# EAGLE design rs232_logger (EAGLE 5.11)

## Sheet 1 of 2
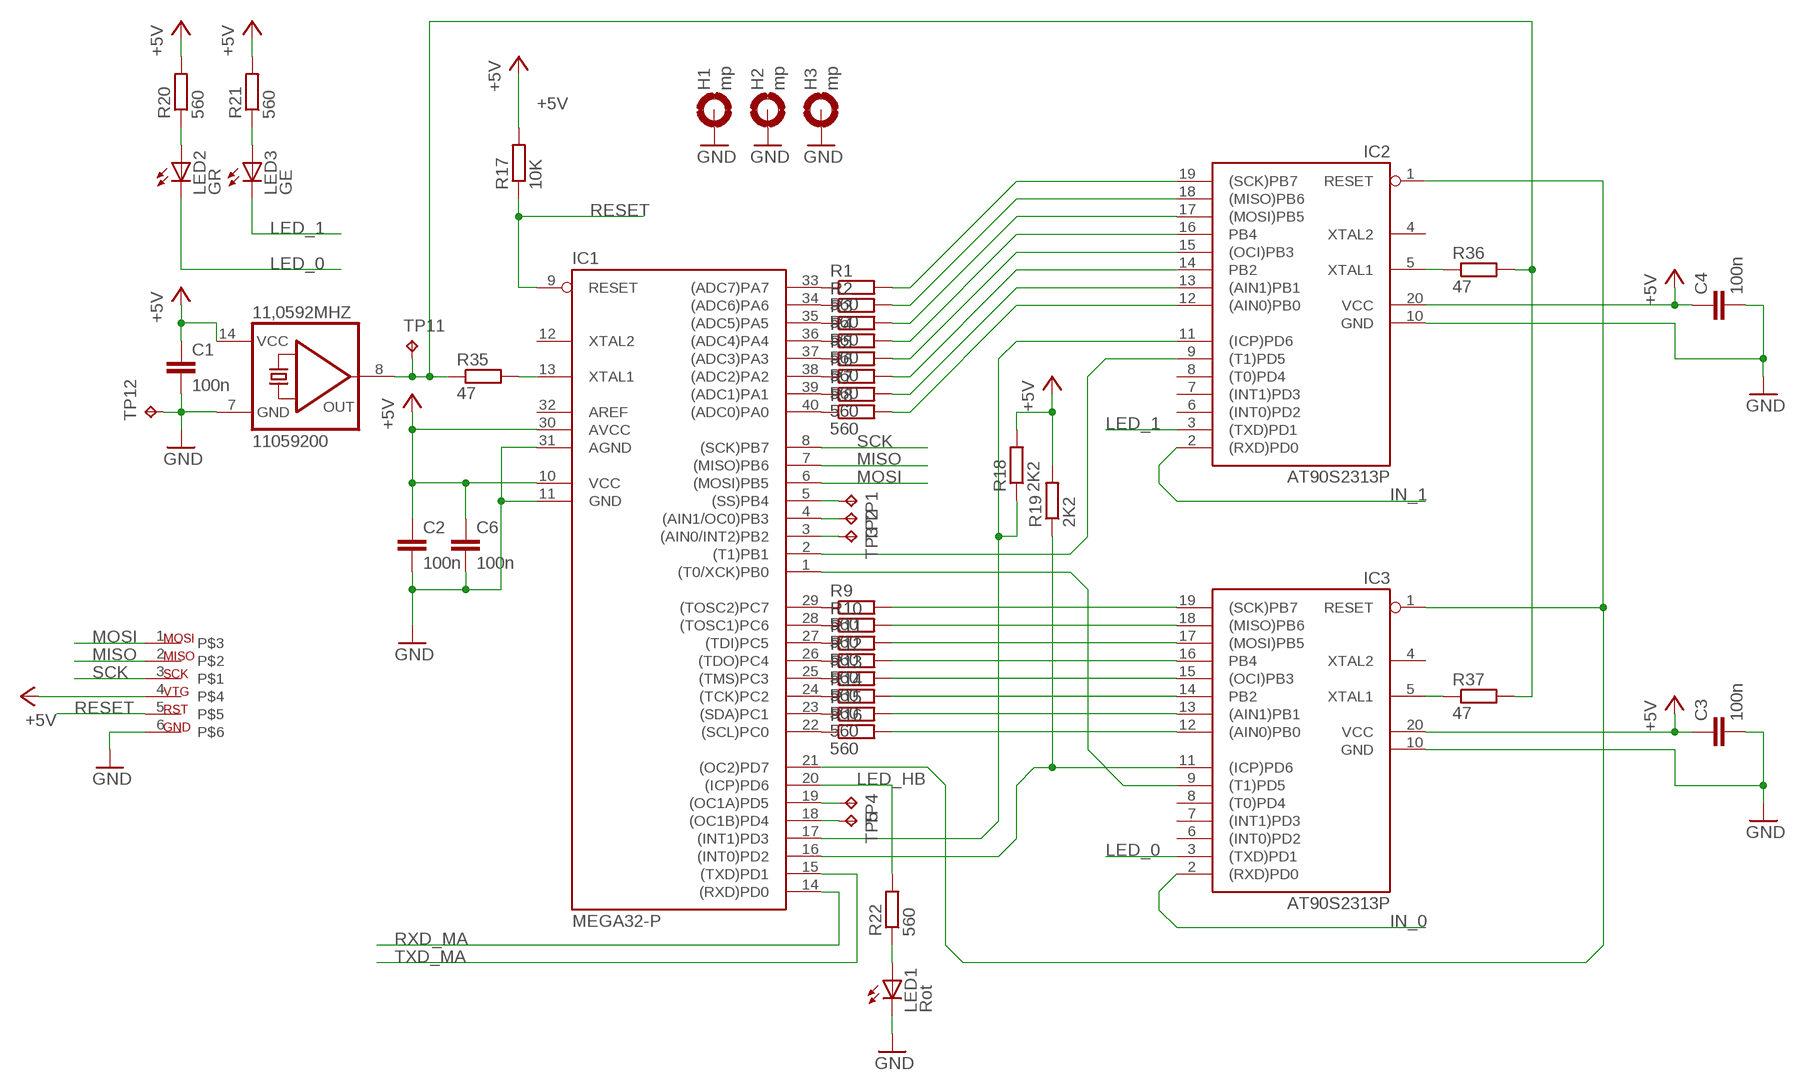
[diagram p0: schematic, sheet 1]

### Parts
11,0592MHZ  11059200  QG5860  [DIL14S]
C1  100n  C-EU050-024X044  [C050-024X044]
C2  100n  C-EU025-024X044  [C025-024X044]
C3  100n  C-EU050-024X044  [C050-024X044]
C4  100n  C-EU050-024X044  [C050-024X044]
C6  100n  C-EU025-024X044  [C025-024X044]
H1  mp  MOUNT-PAD-ROUND3.2  [3,2-PAD]
H2  mp  MOUNT-PAD-ROUND3.2  [3,2-PAD]
H3  mp  MOUNT-PAD-ROUND3.2  [3,2-PAD]
IC1  MEGA32-P  [DIL40]
IC2  AT90S2313P  [DIL20]
IC3  AT90S2313P  [DIL20]
LED1  Rot  LED5MM  [LED5MM]
LED2  GR  LED5MM  [LED5MM]
LED3  GE  LED5MM  [LED5MM]
R1  560  0207/10/LF  [0207/10/LF]
R2  560  0207/10/LF  [0207/10/LF]
R3  560  0207/10/LF  [0207/10/LF]
R4  560  0207/10/LF  [0207/10/LF]
R5  560  0207/10/LF  [0207/10/LF]
R6  560  0207/10/LF  [0207/10/LF]
R7  560  0207/10/LF  [0207/10/LF]
R8  560  0207/10/LF  [0207/10/LF]
R9  560  0207/10/LF  [0207/10/LF]
R10  560  0207/10/LF  [0207/10/LF]
R11  560  0207/10/LF  [0207/10/LF]
R12  560  0207/10/LF  [0207/10/LF]
R13  560  0207/10/LF  [0207/10/LF]
R14  560  0207/10/LF  [0207/10/LF]
R15  560  0207/10/LF  [0207/10/LF]
R16  560  0207/10/LF  [0207/10/LF]
R17  10K  R-EU_0207/10  [0207/10]
R18  2K2  R-EU_0207/10  [0207/10]
R19  2K2  R-EU_0207/10  [0207/10]
R20  560  R-EU_0207/10  [0207/10]
R21  560  R-EU_0207/10  [0207/10]
R22  560  R-EU_0207/10  [0207/10]
R35  47  R-EU_0207/10  [0207/10]
R36  47  R-EU_0207/10  [0207/10]
R37  47  R-EU_0207/10  [0207/10]
TP1  TPPAD1-13Y  [P1-13Y]
TP2  TPPAD1-13Y  [P1-13Y]
TP3  TPPAD1-13Y  [P1-13Y]
TP4  TPPAD1-13Y  [P1-13Y]
TP5  TPPAD1-13Y  [P1-13Y]
TP11  TPPAD1-13  [P1-13]
TP12  TPPAD1-13  [P1-13]
U$1  ISP_6  [M_ISP_6]

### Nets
+5V: 11,0592MHZ.14(VCC) C1.1 C2.1 C3.1 C4.1 C6.1 IC1.10(VCC) IC1.30(AVCC) IC2.20(VCC) IC3.20(VCC) R17.2 R18.2 R19.2 R20.2 R21.2 U$1.4 ; also sheet 2
GND: 11,0592MHZ.7(GND) C1.2 C2.2 C3.2 C4.2 C6.2 H1.B3,2(MOUNT) H2.B3,2(MOUNT) H3.B3,2(MOUNT) IC1.11(GND) IC1.31(AGND) IC2.10(GND) IC3.10(GND) LED1.K(C) TP12.TP U$1.6 ; also sheet 2
IN_0: IC3.2((RXD)PD0) ; also sheet 2
IN_1: IC2.2((RXD)PD0) ; also sheet 2
LED_0: IC3.3((TXD)PD1) LED2.K(C)
LED_1: IC2.3((TXD)PD1) LED3.K(C)
LED_HB: IC1.20((ICP)PD6) R22.2
MISO: IC1.7((MISO)PB6) U$1.2
MOSI: IC1.6((MOSI)PB5) U$1.1
N$1: IC1.33((ADC7)PA7) R1.1
N$2: IC1.34((ADC6)PA6) R2.1
N$3: IC1.35((ADC5)PA5) R3.1
N$4: IC1.36((ADC4)PA4) R4.1
N$5: IC1.37((ADC3)PA3) R5.1
N$6: IC1.38((ADC2)PA2) R6.1
N$7: IC1.39((ADC1)PA1) R7.1
N$8: IC1.40((ADC0)PA0) R8.1
N$9: IC1.29((TOSC2)PC7) R9.1
N$10: IC1.28((TOSC1)PC6) R10.1
N$11: IC1.27((TDI)PC5) R11.1
N$12: IC1.26((TDO)PC4) R12.1
N$13: IC1.25((TMS)PC3) R13.1
N$14: IC1.24((TCK)PC2) R14.1
N$15: IC1.23((SDA)PC1) R15.1
N$16: IC1.22((SCL)PC0) R16.1
N$17: IC2.19((SCK)PB7) R1.2
N$18: IC2.18((MISO)PB6) R2.2
N$19: IC2.17((MOSI)PB5) R3.2
N$20: IC2.16(PB4) R4.2
N$21: IC2.15((OCI)PB3) R5.2
N$22: IC2.14(PB2) R6.2
N$23: IC2.13((AIN1)PB1) R7.2
N$24: IC2.12((AIN0)PB0) R8.2
N$25: IC3.19((SCK)PB7) R9.2
N$26: IC3.18((MISO)PB6) R10.2
N$27: IC3.17((MOSI)PB5) R11.2
N$28: IC3.16(PB4) R12.2
N$29: IC3.15((OCI)PB3) R13.2
N$30: IC3.14(PB2) R14.2
N$31: IC3.13((AIN1)PB1) R15.2
N$32: IC3.12((AIN0)PB0) R16.2
N$33: 11,0592MHZ.8(OUT) R35.1 R36.2 R37.2 TP11.TP
N$34: IC1.21((OC2)PD7) IC2.1(RESET) IC3.1(RESET)
N$35: IC1.16((INT0)PD2) IC3.11((ICP)PD6) R19.1
N$36: IC1.17((INT1)PD3) IC2.11((ICP)PD6) R18.1
N$37: IC1.1((T0/XCK)PB0) IC3.9((T1)PD5)
N$38: IC1.2((T1)PB1) IC2.9((T1)PD5)
N$39: IC1.13(XTAL1) R35.2
N$42: IC2.5(XTAL1) R36.1
N$44: LED2.A R20.1
N$45: IC3.5(XTAL1) R37.1
N$46: LED3.A R21.1
N$48: IC1.18((OC1B)PD4) TP5.TP
N$49: LED1.A R22.1
N$50: IC1.19((OC1A)PD5) TP4.TP
N$52: IC1.3((AIN0/INT2)PB2) TP3.TP
N$53: IC1.4((AIN1/OC0)PB3) TP2.TP
N$54: IC1.5((SS)PB4) TP1.TP
RESET: IC1.9(RESET) R17.1 U$1.5
RXD_MA: IC1.14((RXD)PD0) ; also sheet 2
SCK: IC1.8((SCK)PB7) U$1.3
TXD_MA: IC1.15((TXD)PD1) ; also sheet 2
Unconnected: IC1.12(XTAL2) IC2.4(XTAL2) IC2.6((INT0)PD2) IC2.7((INT1)PD3) IC2.8((T0)PD4) IC3.4(XTAL2) IC3.6((INT0)PD2) IC3.7((INT1)PD3) IC3.8((T0)PD4)

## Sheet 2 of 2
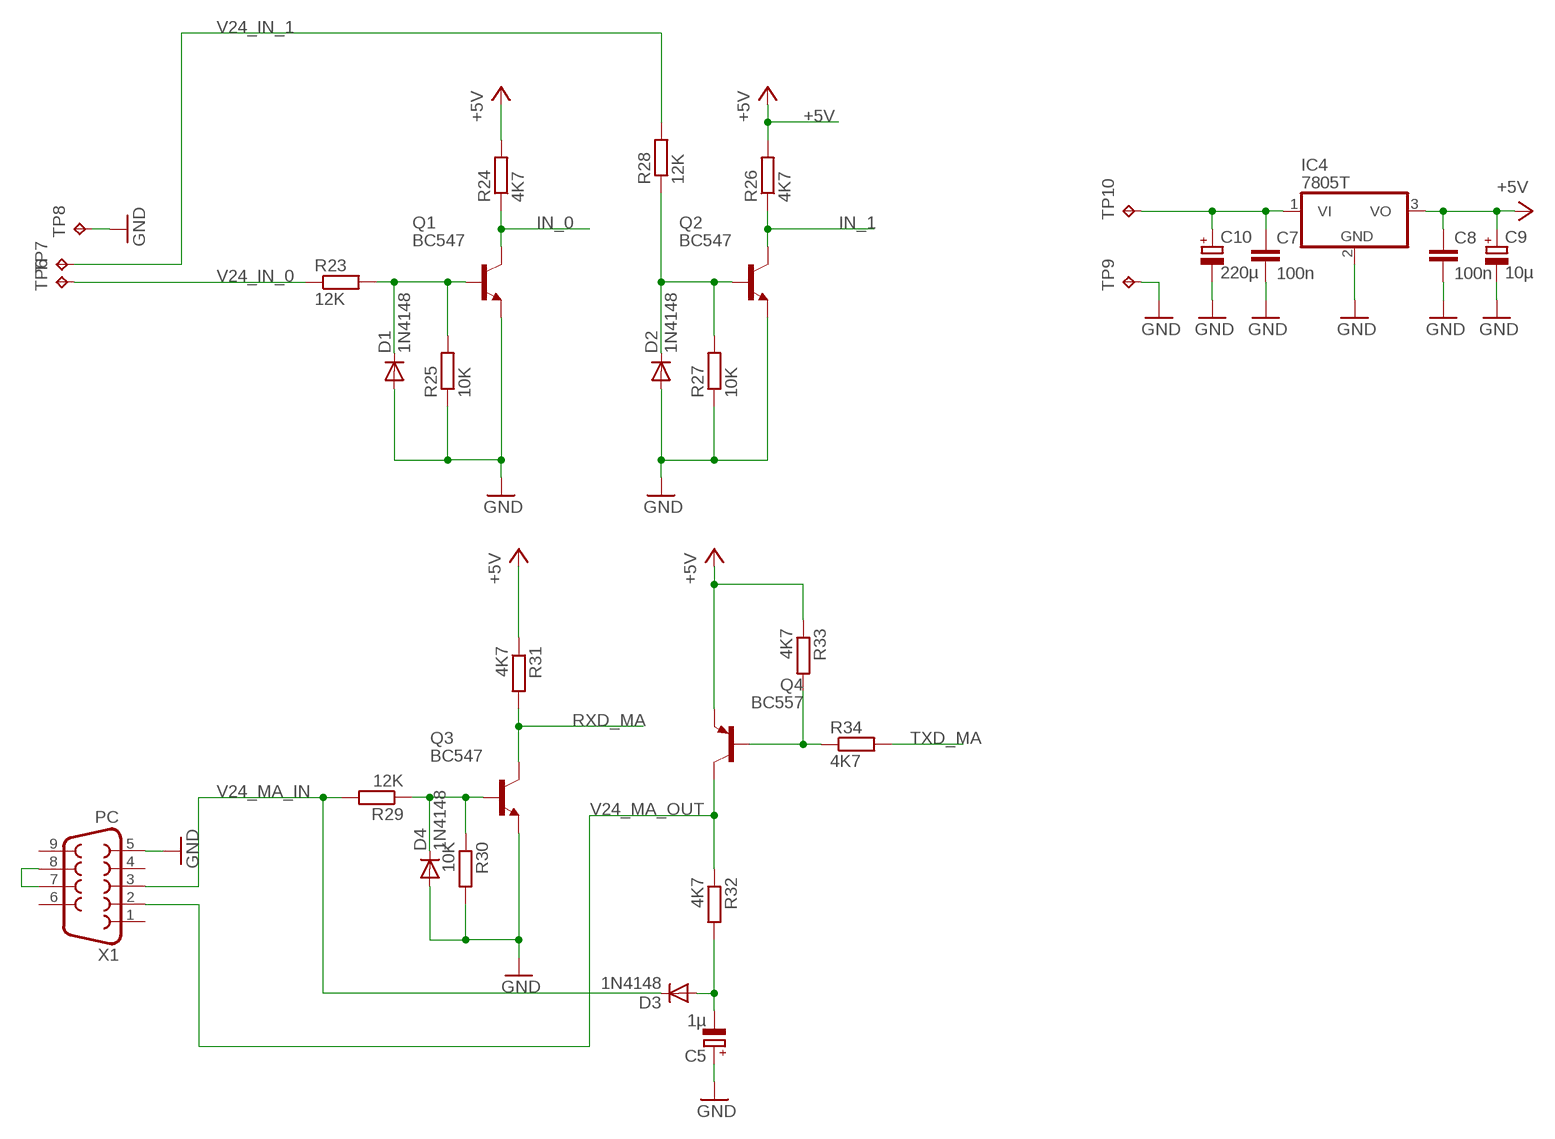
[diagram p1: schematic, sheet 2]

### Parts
C5  1µ  CPOL-EUE2.5-5  [E2,5-5]
C7  100n  C-EU050-024X044  [C050-024X044]
C8  100n  C-EU050-024X044  [C050-024X044]
C9  10µ  CPOL-EUE3.5-8  [E3,5-8]
C10  220µ  CPOL-EUE5-13  [E5-13]
D1  1N4148  1N4148DO35-10  [DO35-10]
D2  1N4148  1N4148DO35-10  [DO35-10]
D3  1N4148  1N4148DO35-10  [DO35-10]
D4  1N4148  1N4148DO35-10  [DO35-10]
IC4  7805T  [TO220H]
Q1  BC547  [TO92-CBE]
Q2  BC547  [TO92-CBE]
Q3  BC547  [TO92-CBE]
Q4  BC557  [TO92-CBE]
R23  12K  R-EU_0207/10  [0207/10]
R24  4K7  R-EU_0207/10  [0207/10]
R25  10K  R-EU_0207/10  [0207/10]
R26  4K7  R-EU_0207/10  [0207/10]
R27  10K  R-EU_0207/10  [0207/10]
R28  12K  R-EU_0207/10  [0207/10]
R29  12K  R-EU_0207/10  [0207/10]
R30  10K  R-EU_0207/10  [0207/10]
R31  4K7  R-EU_0207/10  [0207/10]
R32  4K7  R-EU_0207/10  [0207/10]
R33  4K7  R-EU_0207/10  [0207/10]
R34  4K7  R-EU_0207/10  [0207/10]
TP6  TPPAD1-13Y  [P1-13Y]
TP7  TPPAD1-13Y  [P1-13Y]
TP8  TPPAD1-13Y  [P1-13Y]
TP9  TPPAD1-13Y  [P1-13Y]
TP10  TPPAD1-13Y  [P1-13Y]
X1  PC  F09HP  [F09HP]

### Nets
+5V: C8.1 C9.+ IC4.3(VO) Q4.E R24.2 R26.2 R31.1 R33.1 ; also sheet 1
GND: C5.+ C7.2 C8.2 C9.- C10.- D1.A D2.A D4.A IC4.2(GND) Q1.E Q2.E Q3.E R25.1 R27.1 R30.2 TP8.TP TP9.TP X1.5 ; also sheet 1
IN_0: Q1.C R24.1 ; also sheet 1
IN_1: Q2.C R26.1 ; also sheet 1
N$40: D1.C Q1.B R23.2 R25.2
N$41: C5.- D3.A R32.2
N$43: D2.C Q2.B R27.2 R28.1
N$47: X1.7 X1.8
N$51: D4.C Q3.B R29.1 R30.1
N$56: C7.1 C10.+ IC4.1(VI) TP10.TP
N$57: Q4.B R33.2 R34.1
RXD_MA: Q3.C R31.2 ; also sheet 1
TXD_MA: R34.2 ; also sheet 1
V24_IN_0: R23.1 TP6.TP
V24_IN_1: R28.2 TP7.TP
V24_MA_IN: D3.C R29.2 X1.3
V24_MA_OUT: Q4.C R32.1 X1.2
Unconnected: X1.1 X1.4 X1.6 X1.9

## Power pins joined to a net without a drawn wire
AREF: IC1.32(AREF)

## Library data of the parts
11,0592MHZ = crystal:QG5860: CRYSTAL RESONATOR; OC_FARNELL: unknown; OC_NEWARK: unknown
C1-C4 C6-C8 = !_my_res:C-EU: CAPACITOR, European symbol
C5 = resistor:CPOL-EU: POLARIZED CAPACITOR, European symbol
C9 C10 = !_my_res:CPOL-EU: POLARIZED CAPACITOR, European symbol
D1-D4 = diode:1N4148: DIODE
H1-H3 = holes:MOUNT-PAD-ROUND: MOUNTING PAD, round
IC1 = avr-7:MEGA32-P: MICROCONTROLLER 32 Kbytes FLASH 2 Kbytes SRAM 1 Kbytes EEPROM USART 8-channel 10 bit ADC
IC2 IC3 = atmel:AT90S2313: MICROCONTROLLER 2 Kbytes FLASH 128 bytes SRAM 128 bytes EEPROM UART
IC4 = linear_1:78*: Positive VOLTAGE REGULATOR Source: http://cache.national.com/ds/LM/LM78L05.pdf http://www.fairchildsemi.com/ds/LM/LM7805.pdf
LED1-LED3 = led:LED: LED
Q1-Q3 = !_my_semi:BC547
Q4 = !_my_semi:BC557
R1-R16 = !_my_res:0207/10/LF
R17-R37 = !_my_res:R-EU_: RESISTOR, European symbol
TP1-TP12 = testpad:TP: Test pad
U$1 = !_mylib:ISP_6
X1 = con-subd:F09: SUB-D

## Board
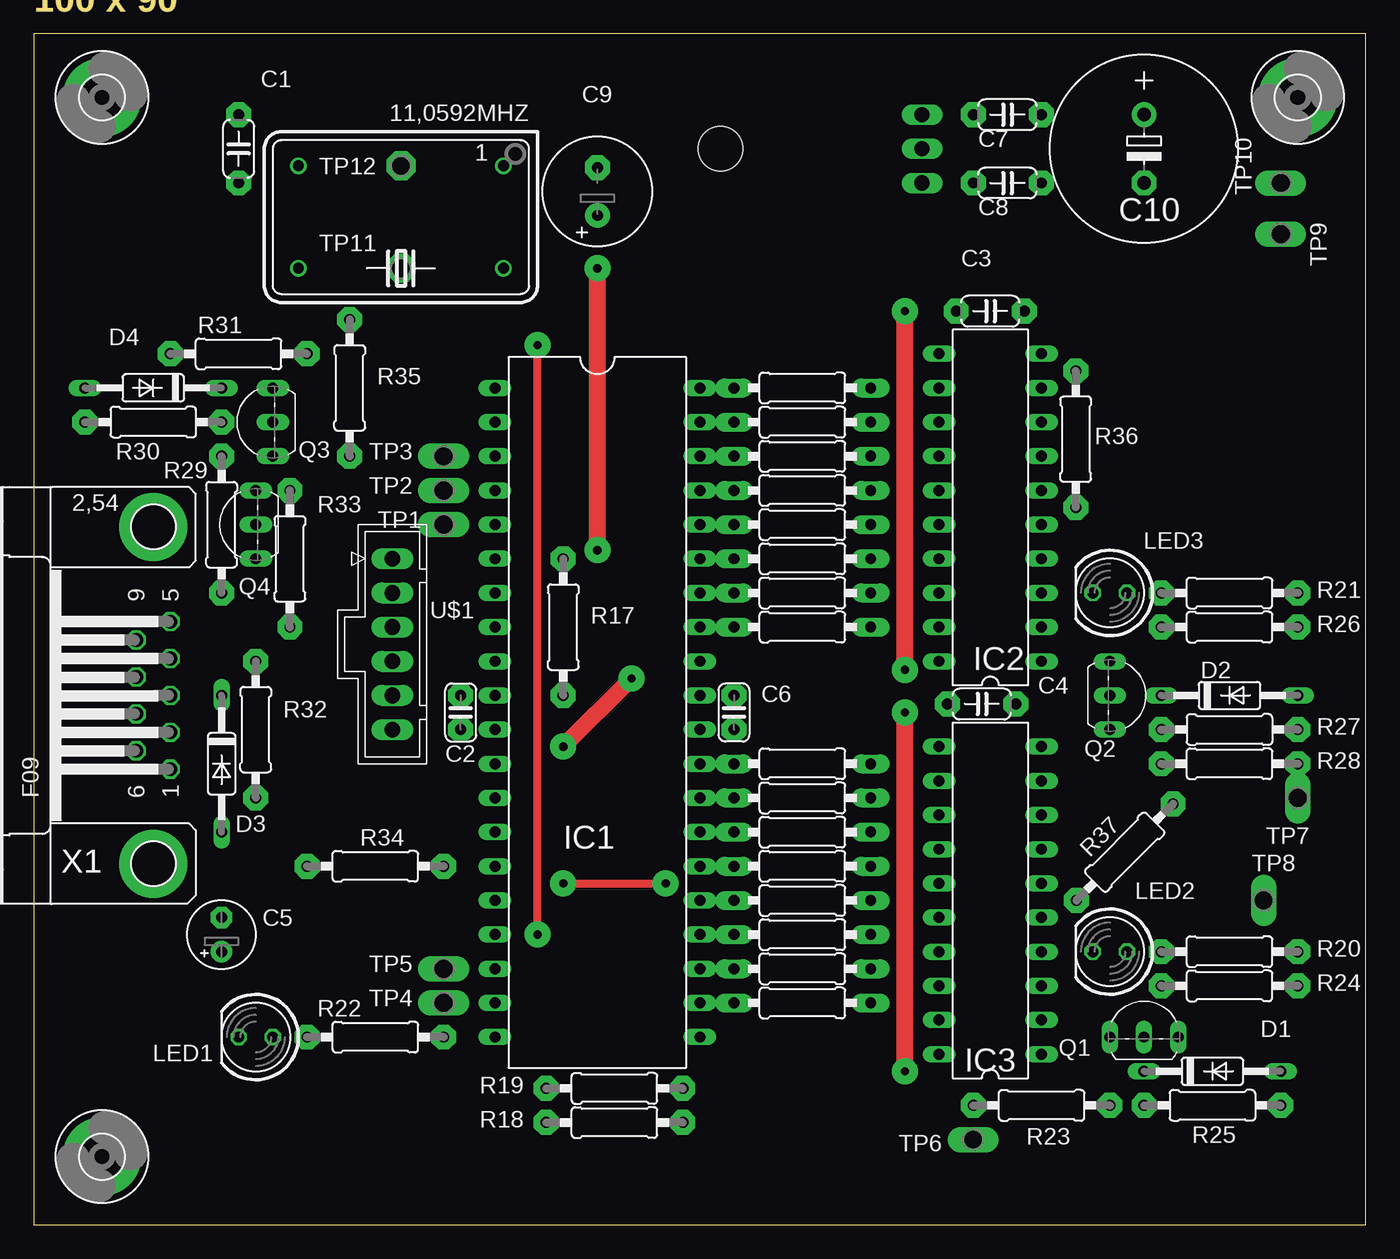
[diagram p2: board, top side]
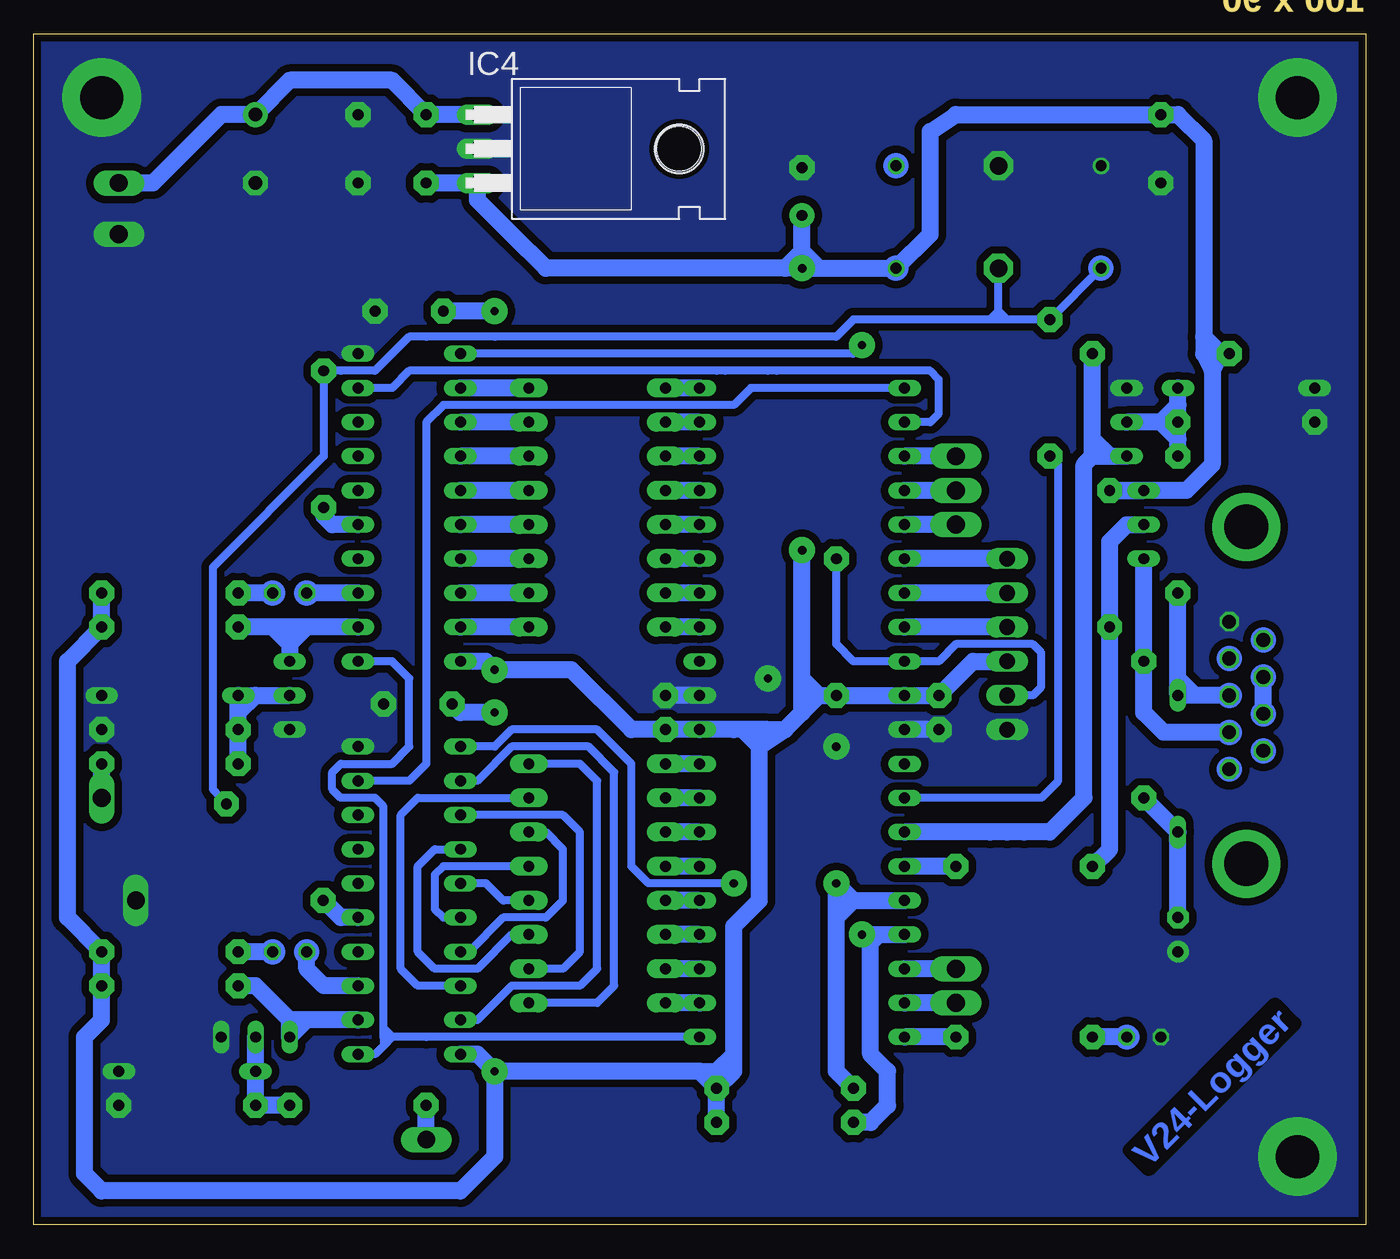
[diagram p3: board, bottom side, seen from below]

Size 99.04 x 88.57 mm. Coordinates in mm from the lower left corner, seen from the top.
Outline: 0,0 99.04,0 99.04,88.57 0,88.57 0,0
Copper layers (1*16): Top 0.035mm / dielectric 1.5mm / Bottom 0.035mm
Design rules "ths 01 and 02 layers": minimum track width 6mil, minimum drill 0.3mm, track to track 6mil, track to pad 6mil, pad to pad 6mil, via to via 6mil, smd to smd 6mil, copper to edge 2mil, drill to drill 10mil, minimum pad ring 8mil, minimum via ring 6mil, stop-mask expansion 3mil, vias tented up to drill 0mil, thermal gap 8mil

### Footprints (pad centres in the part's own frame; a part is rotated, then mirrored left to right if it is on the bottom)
DIL14S = drill 0.813 round: 1 -7.62,-3.81; 7 7.62,-3.81; 8 7.62,3.81; 14 -7.62,3.81
C050-024X044 = drill 0.813 pad 1.85 octagon: 1 -2.54,0; 2 2.54,0
C025-024X044 = drill 0.813 pad 1.85 octagon: 1 -1.27,0; 2 1.27,0
E2,5-5 = drill 0.813 pad 1.6 round: + -1.27,0 | drill 0.813 pad 1.6 octagon: - 1.27,0
E3,5-8 = drill 0.813 pad 1.85 round: + -1.778,0 | drill 0.813 pad 1.85 octagon: - 1.778,0
E5-13 = drill 1.016 pad 1.85 round: + -2.54,0 | drill 1.016 pad 1.85 octagon: - 2.54,0
DO35-10 = drill 0.813 long: A 5.08,0; C -5.08,0
3,2-PAD = drill 3.2 pad 5.842 round: B3,2 0,0
DIL40 = drill 0.813 long: 1 -24.13,-7.62; 2 -21.59,-7.62; 3 -19.05,-7.62; 4 -16.51,-7.62; 5 -13.97,-7.62; 6 -11.43,-7.62; 7 -8.89,-7.62; 8 -6.35,-7.62; 9 -3.81,-7.62; 10 -1.27,-7.62; 11 1.27,-7.62; 12 3.81,-7.62; 13 6.35,-7.62; 14 8.89,-7.62; 15 11.43,-7.62; 16 13.97,-7.62; 17 16.51,-7.62; 18 19.05,-7.62; 19 21.59,-7.62; 20 24.13,-7.62; 21 24.13,7.62; 22 21.59,7.62; 23 19.05,7.62; 24 16.51,7.62; 25 13.97,7.62; 26 11.43,7.62; 27 8.89,7.62; 28 6.35,7.62; 29 3.81,7.62; 30 1.27,7.62; 31 -1.27,7.62; 32 -3.81,7.62; 33 -6.35,7.62; 34 -8.89,7.62; 35 -11.43,7.62; 36 -13.97,7.62; 37 -16.51,7.62; 38 -19.05,7.62; 39 -21.59,7.62; 40 -24.13,7.62
DIL20 = drill 0.813 long: 1 -11.43,-3.81; 2 -8.89,-3.81; 3 -6.35,-3.81; 4 -3.81,-3.81; 5 -1.27,-3.81; 6 1.27,-3.81; 7 3.81,-3.81; 8 6.35,-3.81; 9 8.89,-3.81; 10 11.43,-3.81; 11 11.43,3.81; 12 8.89,3.81; 13 6.35,3.81; 14 3.81,3.81; 15 1.27,3.81; 16 -1.27,3.81; 17 -3.81,3.81; 18 -6.35,3.81; 19 -8.89,3.81; 20 -11.43,3.81
TO220H = drill 1.118 long: 1 -2.54,-10.16; 2 0,-10.16; 3 2.54,-10.16 | hole 3.302: 0,4.826
LED5MM = drill 0.813 octagon: A -1.27,0; K 1.27,0
TO92-CBE = drill 0.813 long: B 0,0; C -2.54,0; E 2.54,0
0207/10/LF = drill 0.813 pad 1.397 long: 1 -5.08,0; 2 5.08,0
0207/10 = drill 0.813 pad 1.85 octagon: 1 -5.08,0; 2 5.08,0
P1-13Y = drill 1.321 pad 1.905 long: TP 0,0
P1-13 = drill 1.321 pad 2.159 octagon: TP 0,0
M_ISP_6 = drill 1.168 long: 1 0,0; 2 2.54,0; 3 5.08,0; 4 7.62,0; 5 10.16,0; 6 12.7,0
F09HP = drill 1.016 octagon: 1 -5.486,-1.27; 2 -2.743,-1.27; 3 0,-1.27; 4 2.743,-1.27; 5 5.486,-1.27; 6 -4.115,1.27; 7 -1.372,1.27; 8 1.372,1.27; 9 4.115,1.27 | drill 3.302 pad 5.08 round: G1 -12.522,0; G2 12.522,0

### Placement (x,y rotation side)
11,0592MHZ  27.3,74.93 180 top
C1  15.24,80.01 270 top
C2  31.75,38.1 270 top
C3  71.12,67.94 0 top
C4  70.48,38.73 0 top
C5  13.97,21.59 90 top
C6  52.07,38.1 90 top
C7  72.39,82.55 0 top
C8  72.39,77.47 0 top
C9  41.91,76.83 90 top
C10  82.55,80.01 270 top
D1  87.63,11.43 0 top
D2  88.9,39.37 0 top
D3  13.97,34.29 270 top
D4  8.89,62.23 180 top
H1  5.08,83.82 0 top
H2  5.08,5.08 0 top
H3  93.98,83.82 0 top
IC1  41.91,38.1 270 top
IC2  71.12,53.34 90 top
IC3  71.12,24.13 90 top
IC4  55.88,80.01 270 bottom
LED1  16.51,13.97 180 top
LED2  80.01,20.32 180 top
LED3  80.01,46.99 180 top
Q1  82.55,13.97 0 top
Q2  80.01,39.37 270 top
Q3  17.78,59.69 90 top
Q4  16.51,52.07 90 top
R1  57.15,44.45 0 top
R2  57.15,46.99 0 top
R3  57.15,49.53 0 top
R4  57.15,52.07 0 top
R5  57.15,54.61 0 top
R6  57.15,57.15 0 top
R7  57.15,59.69 0 top
R8  57.15,62.23 0 top
R9  57.15,34.29 0 top
R10  57.15,31.75 0 top
R11  57.15,29.21 0 top
R12  57.15,26.67 0 top
R13  57.15,24.13 0 top
R14  57.15,21.59 0 top
R15  57.15,19.05 0 top
R16  57.15,16.51 0 top
R17  39.37,44.45 270 top
R18  43.18,7.62 0 top
R19  43.18,10.16 0 top
R20  88.9,20.32 0 top
R21  88.9,46.99 0 top
R22  25.4,13.97 0 top
R23  74.93,8.89 0 top
R24  88.9,17.78 0 top
R25  87.63,8.89 180 top
R26  88.9,44.45 0 top
R27  88.9,36.83 180 top
R28  88.9,34.29 0 top
R29  13.97,52.07 270 top
R30  8.89,59.69 180 top
R31  15.24,64.77 0 top
R32  16.51,36.83 270 top
R33  19.05,49.53 270 top
R34  25.4,26.67 0 top
R35  23.5,62.23 270 top
R36  77.47,58.42 90 top
R37  81.12,27.72 45 top
TP1  30.48,52.07 90 top
TP2  30.48,54.61 90 top
TP3  30.48,57.15 90 top
TP4  30.48,16.51 90 top
TP5  30.48,19.05 90 top
TP6  69.85,6.35 90 top
TP7  93.98,31.75 180 top
TP8  91.44,24.13 0 top
TP9  92.71,73.66 270 top
TP10  92.71,77.47 90 top
TP11  27.3,71.12 0 top
TP12  27.3,78.74 0 top
U$1  26.67,49.53 270 top
X1  8.89,39.37 90 top

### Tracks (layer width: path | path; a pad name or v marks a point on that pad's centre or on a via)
+5V  (via drill 0.61 pad 1.93)
  Top 1.27: v64.77,11.43 v64.77,38.1 | v41.91,50.16 v41.91,71.12 | v64.77,41.27 v64.77,67.94
  Bottom 1.27: 43.18,36.83 41.91,38.1 | 41.91,38.1 40.64,39.37 | 40.64,39.37 R17.2 IC1.10 C2.1 29.21,41.91 U$1.4 | Q4.E R33.1 13.34,54.61 11.43,56.52 11.43,63.5 | R21.2 R26.2 96.52,41.91 96.52,22.86 R20.2 R24.2 93.98,15.24 95.25,13.97 95.25,3.81 93.98,2.54 67.31,2.54 64.77,5.08 v64.77,11.43 | R18.2 R19.2 | R19.2 49.53,11.43 | 49.53,11.43 v64.77,11.43 | 12.06,66.04 12.06,80.64 13.97,82.55 C1.1 30.48,82.55 32.38,81.28 32.38,73.66 11,0592MHZ.14 40.64,71.12 | 12.06,66.04 12.06,64.77 | 12.06,64.77 11.43,63.5 | v64.77,67.94 C3.1 | IC2.20 65.41,41.91 v64.77,41.27 59.05,41.27 54.61,36.83 C6.1 IC1.30 46.99,36.83 46.35,36.83 | C4.1 67.31,38.1 v64.77,38.1 | IC3.20 66.04,12.7 v64.77,11.43 | 44.45,36.83 46.35,36.83 | 44.45,36.83 43.18,36.83 | 45.09,35.56 45.09,24.13 46.99,22.23 46.99,12.7 | 45.09,35.56 44.45,36.83 | 46.99,12.7 46.99,11.43 R19.2 | 45.09,35.56 43.18,36.83 | 45.09,35.56 46.35,36.83 | 49.53,11.43 48.26,11.43 46.99,12.7 | 41.91,40.64 v41.91,50.16 | 40.64,39.37 41.91,40.64 | 41.91,38.1 41.91,40.64 | v41.91,71.12 43.18,71.12 | v41.91,71.12 43.18,71.12 | v41.91,71.12 40.64,71.12 | v41.91,71.12 60.96,71.12 63.5,73.66 66.04,76.2 IC4.3 C8.1 | v41.91,71.12 41.91,72.39 | 41.91,72.39 C9.+ | 40.64,71.12 41.91,72.39 | 43.18,71.12 41.91,72.39 | 12.06,64.77 10.79,64.77 | 10.79,64.77 R31.1 | 12.06,66.04 10.79,64.77 | 10.79,64.77 11.43,63.5
GND  (via drill 0.61 pad 1.93)
  Top 1.27: v39.37,35.56 v44.45,40.64
  Bottom 1.27: C2.2 IC1.11 | IC1.31 C6.2
  pour Bottom (isolate 0.559, rank 2, no thermals): -1.27,90.17 100.33,90.17 100.33,-1.27 -1.27,-1.27
IN_0
  Bottom 1.27: IC3.2 78.74,15.24 | 78.74,15.24 Q1.C 80.01,15.24 | 80.01,15.24 82.55,17.78 R24.1 | 78.74,15.24 80.01,15.24
IN_1
  Bottom 1.27: IC2.2 78.74,44.45 | 78.74,44.45 80.01,44.45 | 80.01,44.45 81.28,44.45 | 81.28,44.45 R26.1 | 80.01,44.45 80.01,43.18 | 80.01,43.18 Q2.C | 78.74,44.45 80.01,43.18 | 80.01,43.18 81.28,44.45
LED_0
  Bottom 1.27: IC3.3 77.47,17.78 78.74,19.05 LED2.K
LED_1
  Bottom 1.27: IC2.3 LED3.K
LED_HB
  Bottom 1.27: R22.2 IC1.20
MISO
  Bottom 1.27: U$1.2 IC1.7
MOSI
  Bottom 1.27: U$1.1 IC1.6
N$1
  Bottom 1.27: IC1.33 R1.1
N$2
  Bottom 1.27: IC1.34 R2.1
N$3
  Bottom 1.27: IC1.35 R3.1
N$4
  Bottom 1.27: IC1.36 R4.1
N$5
  Bottom 1.27: IC1.37 R5.1
N$6
  Bottom 1.27: IC1.38 R6.1
N$7
  Bottom 1.27: IC1.39 R7.1
N$8
  Bottom 1.27: IC1.40 R8.1
N$9
  Bottom 1.27: IC1.29 R9.1
N$10
  Bottom 1.27: IC1.28 R10.1
N$11
  Bottom 1.27: IC1.27 R11.1
N$12
  Bottom 1.27: IC1.26 R12.1
N$13
  Bottom 1.27: IC1.25 R13.1
N$14
  Bottom 1.27: IC1.24 R14.1
N$15
  Bottom 1.27: IC1.23 R15.1
N$16
  Bottom 1.27: IC1.22 R16.1
N$17
  Bottom 1.27: R1.2 IC2.19
N$18
  Bottom 1.27: R2.2 IC2.18
N$19
  Bottom 1.27: R3.2 IC2.17
N$20
  Bottom 1.27: R4.2 IC2.16
N$21
  Bottom 1.27: R5.2 IC2.15
N$22
  Bottom 1.27: R6.2 IC2.14
N$23
  Bottom 1.27: R7.2 IC2.13
N$24
  Bottom 1.27: R8.2 IC2.12
N$25
  Bottom 0.61: IC3.19 66.04,15.24 63.5,17.78 58.42,17.78 57.15,19.05 57.15,33.02 58.42,34.29 R9.2
N$26
  Bottom 0.61: R10.2 70.48,31.75 71.75,30.48 71.75,19.05 70.48,17.78 IC3.18
N$27
  Bottom 0.61: IC3.17 66.67,20.32 64.14,22.86 60.96,22.86 59.69,24.13 59.69,27.94 60.96,29.21 R11.2
N$28
  Bottom 0.61: IC3.16 68.58,22.86 69.22,23.5 69.22,26.04 68.58,26.67 R12.2
N$29
  Bottom 0.61: IC3.15 65.41,25.4 64.14,24.13 R13.2
N$30
  Bottom 0.61: IC3.14 69.22,27.94 70.48,26.67 70.48,20.32 69.22,19.05 66.04,19.05 63.5,21.59 R14.2
N$31
  Bottom 0.61: IC3.13 59.69,30.48 58.42,29.21 58.42,20.32 59.69,19.05 R15.2
N$32
  Bottom 0.61: R16.2 57.15,16.51 55.88,17.78 55.88,33.66 57.78,35.56 63.5,35.56 66.04,33.02 IC3.12
N$33
  Bottom 0.61: R37.2 85.72,32.38 85.72,48.9 77.47,57.15 R36.2 76.2,63.5 73.66,63.5 72.39,64.77 71.12,66.04 69.85,66.04 64.77,66.04 39.37,66.04 38.1,67.31 31.75,67.31 27.94,67.31 | 11,0592MHZ.8 R35.1 26.67,67.31 | 26.67,67.31 27.3,67.31 | 27.3,67.31 27.94,67.31 | 27.3,67.31 27.3,67.94 | 27.3,67.94 TP11.TP | 26.67,67.31 27.3,67.94 | 27.3,67.94 27.94,67.31
N$34
  Bottom 0.61: IC1.21 69.85,13.97 72.39,13.97 | 73.03,13.97 73.03,13.34 | 73.03,13.34 73.66,12.7 IC3.1 | IC2.1 72.39,41.91 71.12,40.64 71.12,35.56 72.39,34.29 76.2,34.29 76.83,33.66 76.83,32.38 76.2,31.75 73.66,31.75 73.03,31.11 73.03,14.61 | 73.03,13.97 73.03,14.61 | 72.39,13.97 73.03,13.97 | 72.39,13.97 73.03,13.34 | 72.39,13.97 73.03,14.61
N$35  (via drill 0.61 pad 1.93)
  Top 0.61: v39.37,25.4 v46.99,25.4
  Bottom 0.61: IC3.11 64.77,35.56 63.5,36.83 57.15,36.83 54.61,34.29 54.61,26.67 53.34,25.4 v46.99,25.4
  Bottom 1.27: IC1.16 36.83,24.13 38.1,24.13 | R19.1 39.37,11.43 39.37,22.86 | 39.37,22.86 39.37,24.13 | 39.37,24.13 v39.37,25.4 38.1,24.13 | 39.37,24.13 38.1,24.13 | 39.37,22.86 38.1,24.13
N$36  (via drill 0.61 pad 1.93)
  Top 0.61: v37.47,21.59 v37.47,65.41
  Bottom 0.61: v37.47,65.41 38.1,64.77 IC2.11
  Bottom 1.27: 36.83,21.59 36.2,21.59 | 36.2,21.59 IC1.17 | 36.83,21.59 v37.47,21.59 36.83,20.95 | R18.1 36.83,7.62 35.56,8.89 35.56,11.43 36.83,12.7 36.83,20.95 | 36.83,20.95 36.83,21.59 | 36.83,20.95 36.2,21.59
N$37
  Bottom 0.61: IC3.9 71.12,33.02 69.85,34.29 69.85,37.47 69.85,38.73 69.85,42.55 69.85,43.18 69.85,59.69 68.58,60.96 53.34,60.96 50.8,60.96 48.26,60.96 46.99,60.96 45.72,62.23 IC1.1
N$38
  Bottom 0.61: IC2.9 72.39,62.23 71.12,63.5 48.26,63.5 47.62,63.5 44.45,63.5 43.81,63.5 32.38,63.5 31.75,62.87 31.75,60.33 32.38,59.69 IC1.2
N$39
  Bottom 0.61: IC1.13 24.13,31.75 22.86,33.02 22.86,56.52 R35.2
N$40
  Bottom 1.27: Q1.B D1.C R25.2 R23.2
N$41
  Bottom 1.27: R32.2 D3.A C5.-
N$42
  Bottom 1.27: IC2.5 76.83,52.07 77.47,52.7 R36.1
N$43
  Bottom 1.27: 82.55,39.37 D2.C 83.82,38.1 | 82.55,39.37 Q2.B | 83.82,38.1 R27.2 R28.1 | 83.82,38.1 82.55,39.37
N$44
  Bottom 1.27: LED2.A R20.1
N$45
  Bottom 1.27: IC3.5 76.2,22.86 77.47,24.13 R37.1
N$46
  Bottom 1.27: LED3.A R21.1
N$47
  Bottom 1.27: X1.7 X1.8
N$48
  Bottom 1.27: TP5.TP IC1.18
N$49
  Bottom 1.27: LED1.A R22.1
N$50
  Bottom 1.27: TP4.TP IC1.19
N$51
  Bottom 1.27: R29.1 13.97,58.42 | 13.97,58.42 R30.1 | R30.1 15.24,59.69 | 13.97,58.42 15.24,59.69 | 15.24,59.69 Q3.B | 13.97,60.96 D4.C | R30.1 13.97,60.96 | 15.24,59.69 13.97,60.96
N$52
  Bottom 1.27: TP3.TP IC1.3
N$53
  Bottom 1.27: TP2.TP IC1.4
N$54
  Bottom 1.27: TP1.TP IC1.5
N$56
  Bottom 1.27: IC4.1 C7.1 72.39,85.09 80.01,85.09 C10.+ 85.09,82.55 90.17,77.47 TP10.TP
N$57
  Bottom 1.27: Q4.B 17.78,52.07 19.05,50.8 R33.2 19.05,27.94 R34.1
RESET
  Bottom 0.61: R17.1 39.37,43.18 38.1,41.91 IC1.9 31.75,41.91 30.48,43.18 24.77,43.18 24.13,42.55 24.13,40.01 24.77,39.37 U$1.5
RXD_MA
  Bottom 1.27: IC1.14 27.94,29.21 26.67,29.21 25.4,29.21 23.5,29.21 20.95,31.75 20.95,56.52 20.32,57.15 | 20.32,57.15 19.05,57.15 | 19.05,57.15 Q3.C | 20.32,57.15 20.32,58.42 | 20.32,58.42 R31.2 | 19.05,57.15 20.32,58.42
SCK
  Bottom 1.27: U$1.3 IC1.8
TXD_MA
  Bottom 1.27: R34.2 IC1.15
V24_IN_0
  Bottom 1.27: TP6.TP R23.1
V24_IN_1
  Bottom 1.27: TP7.TP R28.2
V24_MA_IN
  Bottom 1.27: 13.97,40.64 D3.C 12.7,39.37 | 13.97,40.64 R29.2 | X1.3 12.7,39.37 | 12.7,39.37 13.97,40.64
V24_MA_OUT
  Bottom 1.27: X1.2 15.04,36.63 16.51,38.1 R32.1 Q4.C
(copper drawn outside any net)
  shapes: Bottom circle x16

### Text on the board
Bottom: V24-Logger
Dimension: 100 x 90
